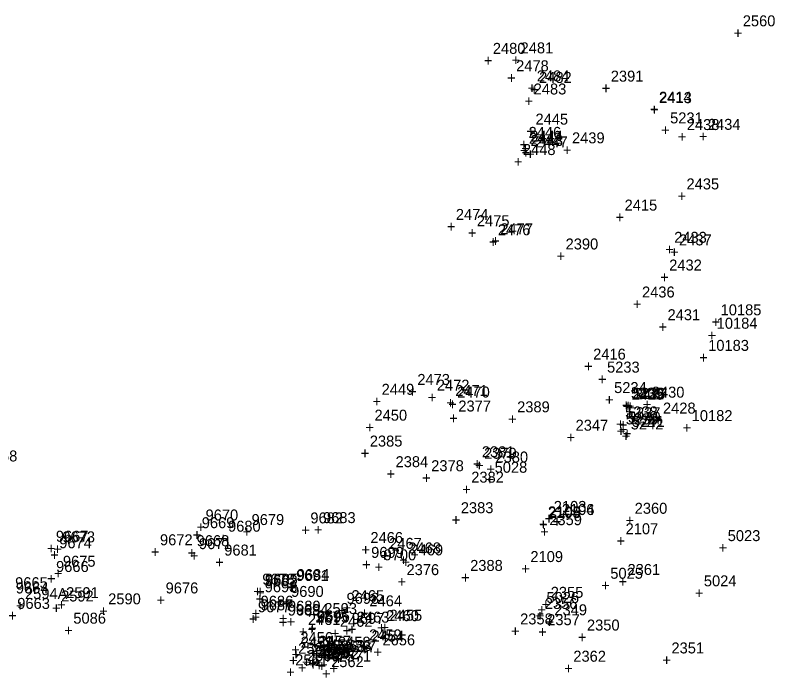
# Model space of a CAD drawing. Extents: x 1136220 to 1137808, y 528804 to 531215.
# Drawn here: x 1136787.3 to 1136960.5, y 529204.4 to 529355.4 of the extents above; entities that cross this region are included whole.
import ezdxf

# ---------------------------------------------------------------- set-up
doc = ezdxf.new("R2010")
doc.units = 0
for name, color, linetype in [('S_Annotation_Label', 7, 'Continuous'), ('S_Buildings', 7, 'Continuous'), ('S_Buildings_Attachments', 7, 'Continuous'), ('S_Buildings_SillElevation', 7, 'Continuous'), ('S_Buildings_Steps_Brick', 7, 'Continuous'), ('S_Curb_Type_1', 7, 'Continuous'), ('S_Curb_Type_3', 7, 'Continuous'), ('S_Drainage_CB', 7, 'Continuous'), ('S_Drainage_Culvert_Top', 7, 'Continuous'), ('S_Drainage_Invert', 7, 'Continuous'), ('S_Drainage_Sump', 7, 'Continuous'), ('S_Ground_Elevation', 7, 'Continuous'), ('S_Ground_SpotElevation', 7, 'Continuous'), ('S_Property_IronPipeFound', 7, 'Continuous'), ('S_Property_Walkways', 7, 'Continuous'), ('S_Roadway_Centerline', 7, 'Continuous'), ('S_Roadway_Drive_Paved', 7, 'Continuous'), ('S_Roadway_Edge_Pavement', 7, 'Continuous'), ('S_Roadway_Painted_Lines', 7, 'Continuous'), ('S_Traffic_Sign_DoublePost', 7, 'Continuous'), ('S_Traffic_Sign_SinglePost', 7, 'Continuous'), ('S_Trees_Bush', 7, 'Continuous'), ('S_Utilities_Gas_Shutoff', 7, 'Continuous'), ('S_Utilities_GuyWire3', 7, 'Continuous'), ('S_Utilities_Hydrant', 7, 'Continuous'), ('S_Utilities_Pole_Joint', 7, 'Continuous'), ('S_Utilities_UG_Gas_Line', 7, 'Continuous'), ('S_Utilities_UG_Sanitary_MH', 7, 'Continuous'), ('S_Utilities_UG_Water_Gate', 7, 'Continuous'), ('S_Utilities_UG_Water_Line', 7, 'Continuous'), ('S_Utilities_UG_Water_Shutoff', 7, 'Continuous')]:
    doc.layers.add(name, color=color, linetype=linetype)

msp = doc.modelspace()

# ---------------------------------------------------------------- texts
at = {"layer": 'S_Annotation_Label'}
for s, p in [('2360', (1136928.57, 529241.79)), ('+', (1136926.51, 529239.04))]:
    msp.add_text(s, height=2.5, dxfattribs=at).set_placement(p)
at = {"layer": 'S_Buildings'}
for s, p in [('2560', (1136953.21, 529352.91)), ('+', (1136951.15, 529350.16)), ('2434', (1136945.26, 529329.31)), ('+', (1136943.2, 529326.56)), ('2433', (1136937.58, 529303.56)), ('+', (1136935.51, 529300.81)), ('10185', (1136948.16, 529287.03)), ('+', (1136946.1, 529284.28)), ('10182', (1136941.57, 529262.91)), ('+', (1136939.51, 529260.16)), ('2362', (1136914.58, 529208.06)), ('+', (1136912.52, 529205.31))]:
    msp.add_text(s, height=2.5, dxfattribs=at).set_placement(p)
at = {"layer": 'S_Buildings_Attachments'}
for s, p in [('2350', (1136917.69, 529215.17)), ('+', (1136915.63, 529212.42)), ('2351', (1136936.95, 529209.95)), ('+', (1136934.89, 529207.2))]:
    msp.add_text(s, height=2.5, dxfattribs=at).set_placement(p)
at = {"layer": 'S_Buildings_SillElevation'}
for s, p in [('10184', (1136947.27, 529283.97)), ('+', (1136945.21, 529281.22)), ('10183', (1136945.32, 529278.92)), ('+', (1136943.26, 529276.17))]:
    msp.add_text(s, height=2.5, dxfattribs=at).set_placement(p)
at = {"layer": 'S_Buildings_Steps_Brick'}
for s, p in [('9691', (1136851.37, 529226.46)), ('9692', (1136844.3, 529225.3)), ('9693', (1136844.22, 529223.9)), ('+', (1136849.31, 529223.71)), ('9690', (1136850.24, 529222.83)), ('+', (1136842.24, 529222.55)), ('+', (1136842.16, 529221.15)), ('9686', (1136843.29, 529220.6)), ('9687', (1136843.29, 529219.76)), ('+', (1136848.17, 529220.08)), ('9689', (1136849.53, 529219.47)), ('+', (1136841.23, 529217.85)), ('9688', (1136849.49, 529218.59)), ('+', (1136841.23, 529217.01)), ('+', (1136847.47, 529216.72)), ('+', (1136847.43, 529215.84))]:
    msp.add_text(s, height=2.5, dxfattribs=at).set_placement(p)
at = {"layer": 'S_Curb_Type_1'}
for s, p in [('5236', (1136928.15, 529267.98)), ('+', (1136926.09, 529265.23)), ('5237', (1136927.01, 529263.57)), ('5240', (1136927.04, 529262.55)), ('5241', (1136927.96, 529261.59)), ('+', (1136924.95, 529260.82)), ('+', (1136924.98, 529259.8)), ('+', (1136925.9, 529258.84))]:
    msp.add_text(s, height=2.5, dxfattribs=at).set_placement(p)
at = {"layer": 'S_Curb_Type_3'}
for s, p in [('2484', (1136906.25, 529340.34)), ('+', (1136904.19, 529337.59)), ('2483', (1136905.54, 529337.37)), ('+', (1136903.48, 529334.62)), ('2476', (1136897.37, 529305.28)), ('+', (1136895.31, 529302.53)), ('2471', (1136887.66, 529268.63)), ('+', (1136885.6, 529265.88)), ('2468', (1136876.97, 529232.75)), ('+', (1136874.91, 529230)), ('2460', (1136871.91, 529217.31)), ('+', (1136869.85, 529214.56)), ('2456', (1136852.35, 529212.3)), ('2459', (1136868.02, 529212.93)), ('2457', (1136856.47, 529211.49)), ('2458', (1136860.92, 529211.25)), ('+', (1136850.29, 529209.55)), ('+', (1136865.96, 529210.18)), ('+', (1136854.41, 529208.74)), ('+', (1136858.86, 529208.5))]:
    msp.add_text(s, height=2.5, dxfattribs=at).set_placement(p)
at = {"layer": 'S_Drainage_CB'}
for s, p in [('2442', (1136904.47, 529326.15)), ('+', (1136902.41, 529323.4)), ('2567', (1136857.74, 529208.78)), ('+', (1136855.68, 529206.03))]:
    msp.add_text(s, height=2.5, dxfattribs=at).set_placement(p)
at = {"layer": 'S_Drainage_Culvert_Top'}
for s, p in [('2445', (1136905.95, 529330.5)), ('+', (1136903.89, 529327.75)), ('2108', (1136908.85, 529240.81)), ('2106', (1136911.95, 529241.5)), ('+', (1136909.89, 529238.75)), ('+', (1136906.79, 529238.06)), ('2107', (1136926.5, 529237.12)), ('+', (1136924.44, 529234.37)), ('2109', (1136904.79, 529230.78)), ('+', (1136902.73, 529228.03)), ('2594A', (1136789.58, 529222.34)), ('+', (1136787.52, 529219.59)), ('2569', (1136853.85, 529208.21)), ('2571', (1136861.05, 529208.07)), ('+', (1136851.79, 529205.46)), ('+', (1136858.98, 529205.32))]:
    msp.add_text(s, height=2.5, dxfattribs=at).set_placement(p)
at = {"layer": 'S_Drainage_Invert'}
for s, p in [('2444', (1136904.76, 529326.61)), ('+', (1136902.7, 529323.86)), ('2105', (1136908.8, 529240.98)), ('2104', (1136911.97, 529241.54)), ('+', (1136909.91, 529238.79)), ('+', (1136906.74, 529238.23)), ('2594', (1136789.58, 529222.34)), ('+', (1136787.52, 529219.59)), ('2570', (1136856.35, 529208.9)), ('2572', (1136858.33, 529208.64)), ('+', (1136854.29, 529206.15)), ('+', (1136856.27, 529205.89))]:
    msp.add_text(s, height=2.5, dxfattribs=at).set_placement(p)
at = {"layer": 'S_Drainage_Sump'}
for s, p in [('2443', (1136904.82, 529325.64)), ('+', (1136902.76, 529322.89)), ('2568', (1136857.22, 529209.53)), ('+', (1136855.16, 529206.78))]:
    msp.add_text(s, height=2.5, dxfattribs=at).set_placement(p)
at = {"layer": 'S_Ground_Elevation'}
for s, p in [('9670', (1136830.74, 529240.26)), ('9679', (1136841.23, 529239.22)), ('9683', (1136857.51, 529239.66)), ('+', (1136828.68, 529237.51)), ('9680', (1136835.87, 529237.7)), ('+', (1136855.45, 529236.91)), ('9673', (1136798.1, 529235.27)), ('+', (1136839.17, 529236.47)), ('9674', (1136797.38, 529233.93)), ('9672', (1136820.35, 529234.61)), ('9671', (1136829.23, 529233.73)), ('+', (1136833.8, 529234.95)), ('+', (1136796.04, 529232.52)), ('+', (1136818.29, 529231.86)), ('9699', (1136868.49, 529231.73)), ('+', (1136795.32, 529231.18)), ('9675', (1136798.22, 529229.71)), ('+', (1136827.17, 529230.98)), ('9700', (1136871.32, 529231.17)), ('+', (1136866.43, 529228.98)), ('+', (1136869.26, 529228.42)), ('+', (1136796.16, 529226.96)), ('9678', (1136843.67, 529225.63)), ('9676', (1136821.64, 529223.63)), ('+', (1136841.61, 529222.88)), ('9698', (1136862.88, 529221.26)), ('+', (1136819.58, 529220.88)), ('9677', (1136842.68, 529219.33)), ('9694', (1136851.3, 529218.71)), ('+', (1136860.82, 529218.51)), ('+', (1136840.62, 529216.58)), ('9695', (1136856.06, 529216.97)), ('9696', (1136856.19, 529217.25)), ('9697', (1136864.06, 529216.69)), ('+', (1136849.23, 529215.96)), ('+', (1136854.13, 529214.5)), ('+', (1136854, 529214.22)), ('+', (1136862, 529213.94)), ('2564', (1136851.84, 529209.87)), ('2565', (1136854.81, 529209.49)), ('2566', (1136856.19, 529209.23)), ('2563', (1136859.69, 529210.41)), ('2561', (1136851.18, 529207.22)), ('+', (1136857.63, 529207.66)), ('+', (1136849.78, 529207.12)), ('+', (1136852.75, 529206.74)), ('+', (1136854.13, 529206.48)), ('2562', (1136859.36, 529206.82)), ('+', (1136849.12, 529204.47)), ('+', (1136857.29, 529204.07))]:
    msp.add_text(s, height=2.5, dxfattribs=at).set_placement(p)
at = {"layer": 'S_Ground_SpotElevation'}
for s, p in [('2446', (1136904.38, 529327.48)), ('2447', (1136905.86, 529325.31)), ('+', (1136902.31, 529324.73)), ('2448', (1136903.09, 529323.56)), ('+', (1136903.8, 529322.56)), ('+', (1136901.03, 529320.81)), ('2474', (1136887.8, 529308.77)), ('+', (1136885.74, 529306.02)), ('2437', (1136938.69, 529302.96)), ('+', (1136936.63, 529300.21)), ('2431', (1136936.06, 529285.91)), ('+', (1136934, 529283.16)), ('2473', (1136879.02, 529271.16)), ('+', (1136876.96, 529268.41)), ('2430', (1136932.47, 529268.25)), ('+', (1136930.41, 529265.5)), ('2359', (1136909.1, 529239.19)), ('2466', (1136868.32, 529235.12)), ('+', (1136907.04, 529236.44)), ('+', (1136866.26, 529232.37)), ('2361', (1136926.93, 529227.84)), ('+', (1136924.87, 529225.09)), ('2465', (1136864.01, 529221.87)), ('+', (1136861.95, 529219.12)), ('2358', (1136902.45, 529216.56)), ('+', (1136900.39, 529213.81))]:
    msp.add_text(s, height=2.5, dxfattribs=at).set_placement(p)
at = {"layer": 'S_Property_IronPipeFound'}
for s, p in [('2432', (1136936.44, 529297.24)), ('+', (1136934.38, 529294.49)), ('2429', (1136927.86, 529267.78)), ('+', (1136925.8, 529265.03))]:
    msp.add_text(s, height=2.5, dxfattribs=at).set_placement(p)
at = {"layer": 'S_Property_Walkways'}
for s, p in [('2480', (1136896.23, 529346.63)), ('2481', (1136902.56, 529346.74)), ('+', (1136894.17, 529343.88)), ('+', (1136900.5, 529343.99)), ('2478', (1136901.54, 529342.66)), ('+', (1136899.48, 529339.91)), ('2475', (1136892.59, 529307.34)), ('+', (1136890.53, 529304.59)), ('2472', (1136883.46, 529269.85)), ('2427', (1136928.61, 529267.86)), ('+', (1136881.4, 529267.1)), ('+', (1136926.55, 529265.11)), ('2428', (1136935.02, 529264.63)), ('+', (1136932.96, 529261.88)), ('9669', (1136829.87, 529238.5)), ('9682', (1136854.64, 529239.59)), ('+', (1136827.81, 529235.75)), ('+', (1136852.58, 529236.84)), ('9668', (1136828.71, 529234.4)), ('2467', (1136872.6, 529233.79)), ('+', (1136826.65, 529231.65)), ('+', (1136870.54, 529231.04)), ('9684', (1136851.53, 529226.67)), ('9685', (1136844.3, 529225.63)), ('+', (1136849.47, 529223.92)), ('+', (1136842.24, 529222.88)), ('2464', (1136868.09, 529220.69)), ('+', (1136866.03, 529217.94)), ('2461', (1136854.07, 529216.43)), ('2462', (1136861.36, 529216.03)), ('2463', (1136865.21, 529216.97)), ('+', (1136852.01, 529213.68)), ('+', (1136859.3, 529213.28)), ('+', (1136863.15, 529214.22))]:
    msp.add_text(s, height=2.5, dxfattribs=at).set_placement(p)
at = {"layer": 'S_Roadway_Centerline'}
for s, p in [('2391', (1136923.12, 529340.3)), ('+', (1136921.06, 529337.55)), ('2390', (1136912.82, 529302.04)), ('+', (1136910.76, 529299.29)), ('2389', (1136901.77, 529264.91)), ('+', (1136899.71, 529262.16)), ('5028', (1136896.64, 529251.14)), ('+', (1136894.58, 529248.39)), ('5023', (1136949.78, 529235.55)), ('+', (1136947.72, 529232.8)), ('2388', (1136891.06, 529228.76)), ('+', (1136889, 529226.01))]:
    msp.add_text(s, height=2.5, dxfattribs=at).set_placement(p)
at = {"layer": 'S_Roadway_Drive_Paved'}
for s, p in [('9658', (1136780.39, 529253.71)), ('9667', (1136796.61, 529235.42)), ('+', (1136794.55, 529232.67)), ('9666', (1136796.66, 529228.52)), ('9665', (1136787.33, 529224.82)), ('+', (1136794.6, 529225.77)), ('9664', (1136787.48, 529223.62)), ('9663', (1136787.82, 529220.1)), ('+', (1136785.76, 529217.35))]:
    msp.add_text(s, height=2.5, dxfattribs=at).set_placement(p)
at = {"layer": 'S_Roadway_Edge_Pavement'}
for s, p in [('2482', (1136906.77, 529340.01)), ('+', (1136904.71, 529337.26)), ('5231', (1136936.65, 529330.78)), ('+', (1136934.59, 529328.03)), ('2477', (1136897.94, 529305.5)), ('+', (1136895.88, 529302.75)), ('5233', (1136922.27, 529273.97)), ('+', (1136920.21, 529271.22)), ('2470', (1136888.1, 529268.28)), ('5234', (1136923.88, 529269.3)), ('5235', (1136927.72, 529268.04)), ('+', (1136921.81, 529266.55)), ('+', (1136886.04, 529265.53)), ('+', (1136925.66, 529265.29)), ('5238', (1136926.39, 529263.75)), ('5239', (1136926.53, 529262.16)), ('5242', (1136927.68, 529261.01)), ('+', (1136924.33, 529261)), ('+', (1136924.47, 529259.41)), ('+', (1136925.62, 529258.26)), ('2469', (1136877.46, 529232.3)), ('+', (1136875.4, 529229.55)), ('5025', (1136923.01, 529226.97)), ('5024', (1136944.34, 529225.25)), ('2355', (1136909.43, 529222.63)), ('+', (1136920.95, 529224.22)), ('5026', (1136908.46, 529221.45)), ('+', (1136942.28, 529222.5)), ('+', (1136907.37, 529219.88)), ('2356', (1136908.08, 529220.08)), ('+', (1136906.4, 529218.7)), ('5086', (1136800.6, 529216.74)), ('2455', (1136872.69, 529217.41)), ('+', (1136906.01, 529217.33)), ('2357', (1136908.63, 529216.39)), ('+', (1136870.63, 529214.66)), ('+', (1136798.54, 529213.99)), ('2454', (1136868.56, 529212.65)), ('+', (1136906.57, 529213.64)), ('2451', (1136852.44, 529211.26)), ('2452', (1136857.11, 529210.64)), ('2453', (1136861.16, 529210.5)), ('+', (1136866.5, 529209.9)), ('+', (1136850.38, 529208.51)), ('+', (1136855.05, 529207.89)), ('+', (1136859.1, 529207.75))]:
    msp.add_text(s, height=2.5, dxfattribs=at).set_placement(p)
at = {"layer": 'S_Roadway_Painted_Lines'}
for s, p in [('2656', (1136871.07, 529211.79)), ('2657', (1136862.12, 529210.23)), ('+', (1136860.05, 529207.48)), ('+', (1136869.01, 529209.04))]:
    msp.add_text(s, height=2.5, dxfattribs=at).set_placement(p)
at = {"layer": 'S_Traffic_Sign_DoublePost'}
for s, p in [('2449', (1136870.88, 529268.91)), ('+', (1136868.82, 529266.16)), ('2450', (1136869.25, 529263.01)), ('+', (1136867.19, 529260.26))]:
    msp.add_text(s, height=2.5, dxfattribs=at).set_placement(p)
at = {"layer": 'S_Traffic_Sign_SinglePost'}
for s, p in [('2385', (1136868.18, 529257.11)), ('+', (1136866.11, 529254.36)), ('2593', (1136857.82, 529218.94)), ('+', (1136855.76, 529216.19))]:
    msp.add_text(s, height=2.5, dxfattribs=at).set_placement(p)
at = {"layer": 'S_Trees_Bush'}
for s, p in [('9681', (1136835, 529232.26)), ('+', (1136832.93, 529229.51))]:
    msp.add_text(s, height=2.5, dxfattribs=at).set_placement(p)
at = {"layer": 'S_Utilities_Gas_Shutoff'}
for s, p in [('2435', (1136940.38, 529315.73)), ('+', (1136938.32, 529312.98))]:
    msp.add_text(s, height=2.5, dxfattribs=at).set_placement(p)
at = {"layer": 'S_Utilities_GuyWire3'}
for s, p in [('2592', (1136797.81, 529221.79)), ('2591', (1136798.96, 529222.55)), ('+', (1136796.9, 529219.8)), ('+', (1136795.75, 529219.04))]:
    msp.add_text(s, height=2.5, dxfattribs=at).set_placement(p)
at = {"layer": 'S_Utilities_Hydrant'}
for s, p in [('2384', (1136874.06, 529252.41)), ('+', (1136872, 529249.66))]:
    msp.add_text(s, height=2.5, dxfattribs=at).set_placement(p)
at = {"layer": 'S_Utilities_Pole_Joint'}
for s, p in [('2438', (1136940.45, 529329.26)), ('+', (1136938.39, 529326.51)), ('2590', (1136808.54, 529221.14)), ('+', (1136806.48, 529218.39)), ('2349', (1136910.26, 529218.65)), ('+', (1136908.2, 529215.9))]:
    msp.add_text(s, height=2.5, dxfattribs=at).set_placement(p)
at = {"layer": 'S_Utilities_UG_Gas_Line'}
for s, p in [('2414', (1136934.1, 529335.51)), ('2413', (1136934.16, 529335.39)), ('+', (1136932.04, 529332.76)), ('+', (1136932.1, 529332.64)), ('2415', (1136926.27, 529310.9)), ('+', (1136924.21, 529308.15)), ('2416', (1136919.1, 529276.93)), ('+', (1136917.04, 529274.18)), ('2377', (1136888.37, 529265.1)), ('+', (1136886.31, 529262.35)), ('2347', (1136915.1, 529260.72)), ('+', (1136913.04, 529257.97)), ('2376', (1136876.55, 529227.8)), ('+', (1136874.49, 529225.05))]:
    msp.add_text(s, height=2.5, dxfattribs=at).set_placement(p)
at = {"layer": 'S_Utilities_UG_Sanitary_MH'}
for s, p in [('2103', (1136910.12, 529242.21)), ('+', (1136908.06, 529239.46))]:
    msp.add_text(s, height=2.5, dxfattribs=at).set_placement(p)
at = {"layer": 'S_Utilities_UG_Water_Gate'}
for s, p in [('2379', (1136894.24, 529254.33)), ('2378', (1136882.18, 529251.49)), ('+', (1136892.18, 529251.58)), ('+', (1136880.11, 529248.74))]:
    msp.add_text(s, height=2.5, dxfattribs=at).set_placement(p)
at = {"layer": 'S_Utilities_UG_Water_Line'}
for s, p in [('2439', (1136914.28, 529326.23)), ('+', (1136912.22, 529323.48)), ('2381', (1136893.73, 529254.67)), ('2380', (1136896.83, 529253.48)), ('+', (1136891.67, 529251.92)), ('2382', (1136891.31, 529248.88)), ('+', (1136894.77, 529250.73)), ('+', (1136889.25, 529246.13)), ('2383', (1136888.93, 529241.92)), ('+', (1136886.86, 529239.17))]:
    msp.add_text(s, height=2.5, dxfattribs=at).set_placement(p)
at = {"layer": 'S_Utilities_UG_Water_Shutoff'}
for s, p in [('2436', (1136930.24, 529291.09)), ('+', (1136928.17, 529288.34))]:
    msp.add_text(s, height=2.5, dxfattribs=at).set_placement(p)

doc.saveas('drawing.dxf')
